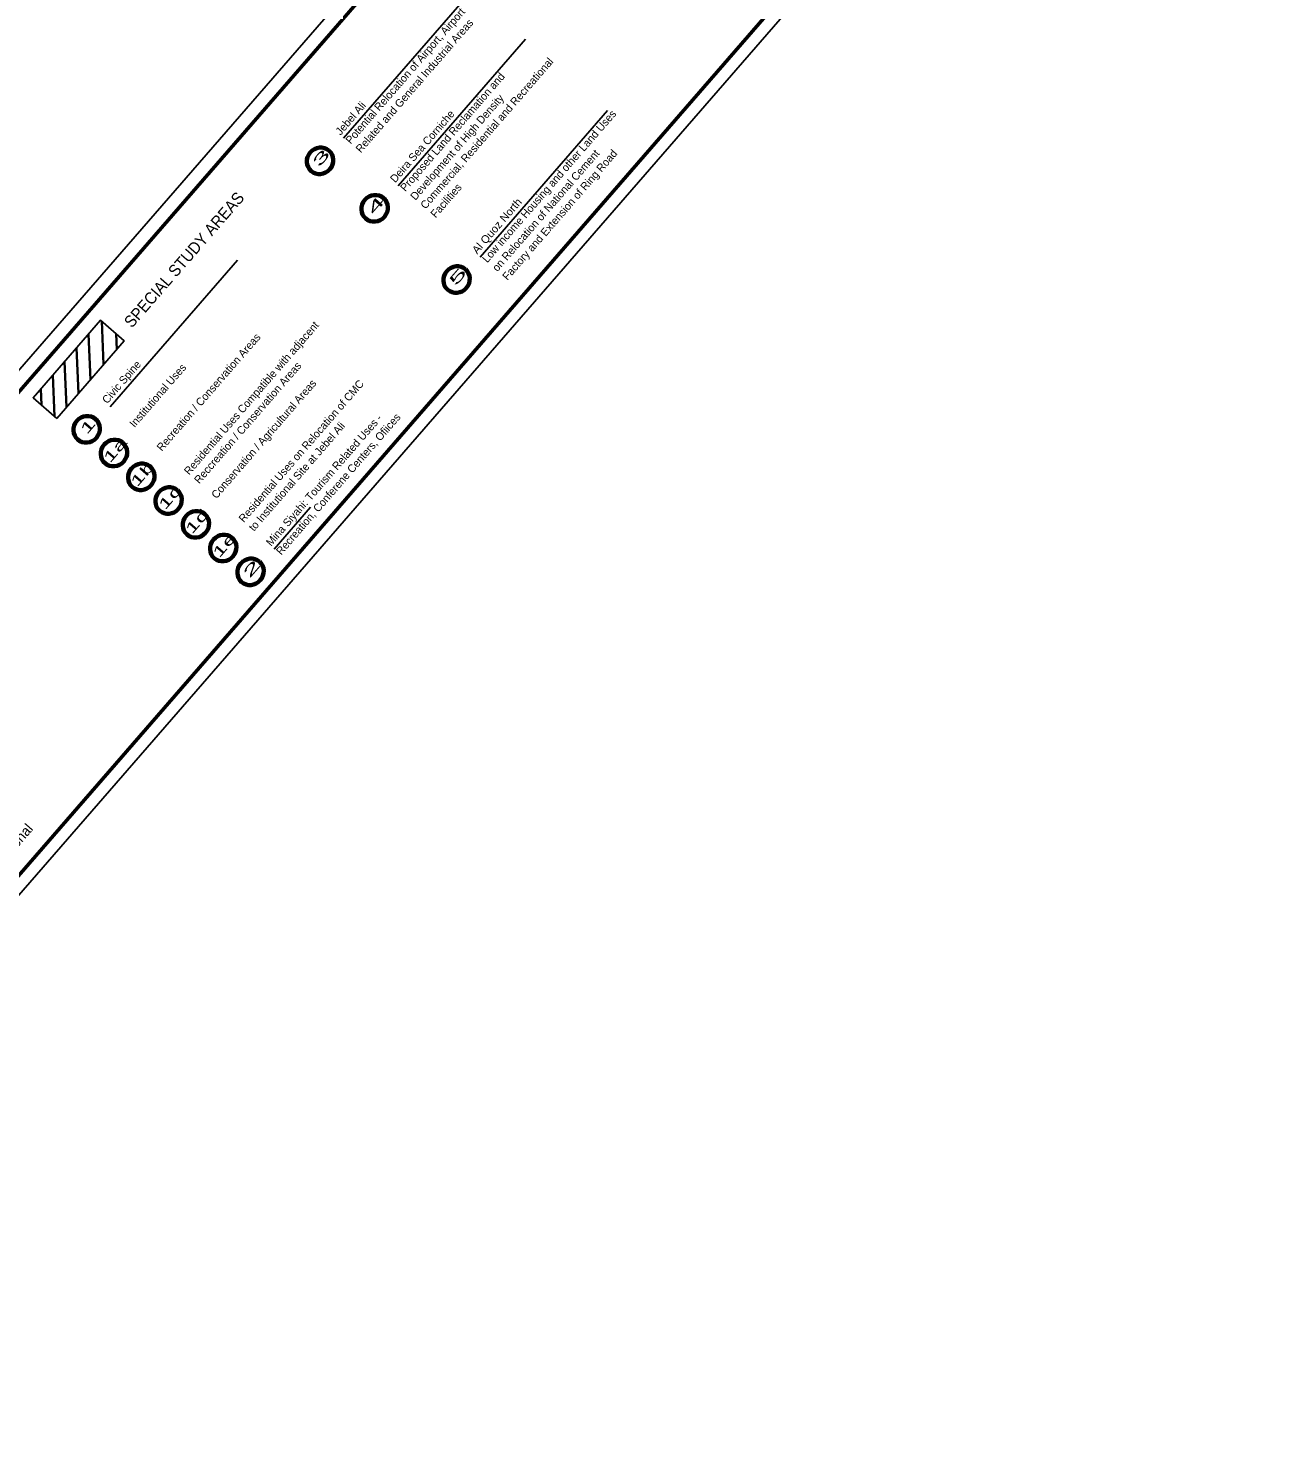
# Model space of a CAD drawing. Extents: x 290038 to 370218, y 2722677 to 2808586.
# Drawn here: x 335265 to 370218, y 2722677 to 2762800 of the extents above; entities that cross this region are included whole.
import ezdxf
from ezdxf.enums import TextEntityAlignment as Align

# ---------------------------------------------------------------- set-up
doc = ezdxf.new("R2010")
doc.units = 0
doc.header["$LTSCALE"] = 88
for name, color, linetype, lineweight in [('20', 7, 'Continuous', 13), ('28', 7, 'Continuous', 35), ('29', 7, 'Continuous', 13)]:
    doc.layers.add(name, color=color, linetype=linetype, lineweight=lineweight)

msp = doc.modelspace()

# ---------------------------------------------------------------- linework, layer by layer
at = {"layer": '20', "lineweight": 25}
for p, q in [((344122.07, 2759713.83), (347705.91, 2763836.57)), ((345658.28, 2758378.42), (349242.13, 2762501.16)), ((347962.6, 2756375.31), (351546.44, 2760498.05)), ((337559.3, 2752164.22), (341143.14, 2756286.96)), ((342167.93, 2748158), (343195.15, 2749339.67))]:
    msp.add_line(p, q, dxfattribs=at)
for points in [[(313980.4, 2729027.31), (362912.77, 2785317.56), (370218.38, 2778966.9), (321286.01, 2722676.64)], [(336061.77, 2751838.04), (337955.95, 2754017.04), (337286.55, 2754598.94), (335392.38, 2752419.94)]]:
    msp.add_lwpolyline(points, close=True, dxfattribs=at)
at = {"layer": '20', "lineweight": 53}
msp.add_lwpolyline([(314544.71, 2729066.77), (349767.76, 2769586.26), (356498.65, 2763735.18), (321275.6, 2723215.69)], close=True, dxfattribs=at)
at = {"layer": '28'}
for p, q in [((337375.75, 2753349.6), (337321.88, 2754568.23)), ((337004.63, 2752922.67), (336947.75, 2754209.19)), ((337746.87, 2753776.53), (337727.46, 2754215.66)), ((336670.62, 2752538.44), (336613.75, 2753824.96)), ((336336.61, 2752154.2), (336279.74, 2753440.73)), ((335997.11, 2751894.25), (335945.73, 2753056.49)), ((335632.08, 2752211.56), (335611.72, 2752672.26))]:
    msp.add_line(p, q, dxfattribs=at)
at = {"layer": '29', "lineweight": 60}
for centre in [(343462.36, 2759079.8), (344998.57, 2757744.39), (347302.88, 2755741.28), (336899.59, 2751530.19), (337667.69, 2750862.49), (338435.8, 2750194.79), (339203.9, 2749527.08), (339972.01, 2748859.38), (340740.11, 2748191.68), (341508.22, 2747523.97)]:
    msp.add_ellipse(centre, major_axis=(250.41, 288.07), ratio=0.95, dxfattribs=at)

# ---------------------------------------------------------------- texts
at = {"layer": '20'}
for s, height, p in [('Potential Relocation of Airport, Airport', 220.4, (344325.06, 2759535.12)), ('Related and General Industrial Areas', 220.4, (344609.32, 2759288.01)), ('Commercial, Residential and Recreational', 220.4, (346429.79, 2757705.5)), ('Proposed Land Reclamation and', 220.4, (345861.27, 2758199.71)), ('Development of High Density', 220.4, (346145.53, 2757952.6)), ('Jebel Ali', 220.4, (344040.8, 2759782.22)), ('Deira Sea Corniche', 220.4, (345577.02, 2758446.81)), ('Low income Housing and other Land Uses', 220.4, (348165.59, 2756196.6)), ('on Relocation of National Cement', 220.4, (348449.85, 2755949.49)), ('Factory and Extension of Ring Road', 220.4, (348734.11, 2755702.39)), ('Facilities', 220.4, (346714.05, 2757458.4)), ('Residential Uses Compatible with adjacent', 220.4, (339782.35, 2750229.5)), ('Recreation / Conservation Areas', 220.4, (339014.24, 2750897.21)), ('Civic Spine', 220.4, (337478.03, 2752232.61)), ('Institutional Uses', 220.4, (338246.14, 2751564.91)), ('Reccreation / Conservation Areas', 220.4, (340066.61, 2749982.4)), ('Conservation / Agricultural Areas', 220.4, (340550.45, 2749561.8)), ('Residential Uses on Relocation of CMC', 220.4, (341318.56, 2748894.1)), ('to Institutional Site at Jebel Ali ', 220.4, (341602.82, 2748646.99)), ('Mina Siyahi: Tourism Related Uses -', 220.4, (342086.66, 2748226.39)), ('Recreation, Conferene Centers, Ofiices', 220.4, (342370.92, 2747979.29)), ('Institutional', 285, (334148.33, 2738830.35))]:
    msp.add_text(s, height=height, rotation=49, dxfattribs=at).set_placement(p)
for s, height, width, p in [('SPECIAL STUDY AREAS', 330.6, 0.95, (338171.68, 2754359.34)), ('Al Quoz North', 220.4, 1.05, (347881.33, 2756443.7))]:
    msp.add_text(s, height=height, rotation=49, dxfattribs=dict(at, width=width)).set_placement(p)
at = {"layer": '29'}
for s, width, p in [('3', 2.35, (343600.68, 2759070.26)), ('4', 2.45, (345136.89, 2757734.85)), ('5', 2.4, (347441.21, 2755731.74)), ('1', 1.95, (337037.91, 2751520.65)), ('1a', 1.8, (337806.02, 2750852.95)), ('1b', 1.85, (338574.12, 2750185.25)), ('1c', 1.8, (339342.23, 2749517.54)), ('1d', 1.8, (340110.33, 2748849.84)), ('1e', 1.8, (340878.44, 2748182.14)), ('2', 2.4, (341646.54, 2747514.43))]:
    msp.add_text(s, height=285, rotation=49, dxfattribs=dict(at, width=width)).set_placement(p, align=Align.CENTER)

doc.saveas('drawing.dxf')
